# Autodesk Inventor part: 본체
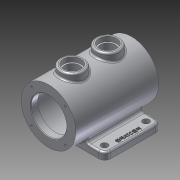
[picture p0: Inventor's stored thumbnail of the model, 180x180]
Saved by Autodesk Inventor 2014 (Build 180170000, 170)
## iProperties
Created: 2014-12
Part Number: 본체
Material: 알루미늄 6061
Document SubType Name: Modeling
Designer: Owner
Density: 2.71 g/cm^3
Appearance: 알루미늄 - 평지
Mass: 1293.91 g
Surface Area: 1040.14 cm^2
Volume: 477.456 cm^3
Author: Owner
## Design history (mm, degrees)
sketch "스케치1"
  geometry: C1 r 46 at (0, 0); 1 further point
  constraints: 1 centre point, 1 coincident
  dimensions: "d0" = 92 diameter of C1
extrude "돌출1" new body sketch "스케치1" stored distance "d1" = 140; taper "d2" = 0 deg
node "작업 평면1"
sketch "스케치2"
  geometry: L1 (-38, 65)-(-50, 65); L2 (-50, 65)-(-50, -65); L3 (-50, -65)-(-38, -65); L4 (-38, 38.884)-(-38, 65); L5 (-38, -38.884)-(-38, -65); A1 r 46 centre (0, 0) between (-38, -25.923) and (-38, 25.923) reference; A2 r 46 centre (0, 0) between (-29.765, -35.072) and (-29.765, 35.072); A3 r 5 centre (-33, 38.884) between (-38, 38.884) and (-29.765, 35.072); A4 r 5 centre (-33, -38.884) between (-29.765, -35.072) and (-38, -38.884); 2 further points
  constraints: 10 end point, 10 point on circle, 4 tangent, 3 centre point, 2 parallel, 2 point on line, 1 coincident, 1 collinear, 1 equal radius, 1 horizontal, 1 horizontal alignment, 1 midpoint, 1 perpendicular
  dimensions: "d4" = 130 distance of L1.end L2.end; "d5" = 50 distance from line of point (0, 0) L2; "d6" = 12 distance of L1.start L1.end; "d7" = 12 distance between parallel lines of L2 L5; "d8" = 5 radius of A3
extrude "돌출2" join sketch "스케치2" distance "d9" = 95; taper "d10" = 0 deg
hole "구멍1" diameter "d13" = 60; stored, may be unused: countersink angle "d17" = 90 deg, drill point angle "d19" = 118 deg; dims "d11" = 10, "d12" = 10, "d14" = 6, "d15" = 4, "d16" = 2, "d18" = 8
node "작업 평면2"
sketch "스케치3"
  geometry: C1 r 37.5 at (0, 0); 1 further point
  constraints: 1 centre point, 1 coincident
  dimensions: "d21" = 75 diameter of C1
extrude "돌출3" cut sketch "스케치3" distance "d22" = 116; taper "d23" = 0 deg
node "작업 평면3"
sketch "스케치4"
  geometry: L1 (-70, 46)-(-70, -46) reference; L2 (70, -46)-(70, 46) reference; C1 r 20 at (-30, 0); C2 r 20 at (30, 0); 1 further point
  constraints: 2 centre point, 2 horizontal alignment
  dimensions: "d25" = 40 diameter of C1; "d27" = 40 distance from line of L1 C1.centre; "d29" = 40 diameter of C2; "d30" = 40 distance from line of L2 C2.centre
extrude "돌출4" join sketch "스케치4" stored distance "d31" = 116; taper "d32" = 0 deg
hole "구멍2" diameter "d35" = 25; stored, may be unused: countersink angle "d39" = 90 deg, drill point angle "d41" = 118 deg; dims "d33" = 10, "d34" = 10, "d36" = 6, "d37" = 30, "d38" = 8, "d40" = 8
hole "구멍3" diameter "d44" = 25; stored, may be unused: countersink angle "d48" = 90 deg, drill point angle "d50" = 118 deg; dims "d42" = 10, "d43" = 10, "d45" = 6, "d46" = 30, "d47" = 8, "d49" = 8
sketch "스케치5"
  geometry: L1 (0, 0)-(26.116, 0) reference; L2 (26.116, -95)-(0, -95) reference; L3 (26.116, 0)-(26.116, -95) reference; 3 further points
  dimensions: "d53" = 13 distance from line of L3 point (13.116, -12.5); "d54" = 12.5 distance from line of L1 point (13.116, -12.5); "d55" = 12.5 distance from line of L2 point (13.116, -82.5); "d56" = 13 distance from line of L3 point (13.116, -82.5)
hole "구멍4" sketch "스케치5" at (13.116, -12.5), (13.116, -82.5) diameter "d57" = 11; stored, may be unused: countersink angle "d61" = 90 deg, drill point angle "d63" = 118 deg; dims "d58" = 6, "d59" = 30, "d60" = 8, "d62" = 8
sketch "스케치6"
  geometry: L1 (26.116, 0)-(26.116, -95) reference; C1 r 5.5 at (13.116, -82.5) reference; 2 further points
  constraints: 1 other
  dimensions: "d64" = 35 vertical distance of C1.centre point (18.116, -47.5); "d65" = 8 distance from line of L1 point (18.116, -47.5)
feature "엠보싱1" sketch "스케치6" dims "d66" = 1, "d67" = 0
fillet "모깎기1" dims "d68" = 10
fillet "모깎기2" dims "d69" = 3
fillet "모깎기3" dims "d70" = 3
fillet "모깎기4" dims "d71" = 3
chamfer "모따기1" distance "d72" = 1; stored, may be unused: second distance "d73" = 2, angle "d74" = 45 deg
chamfer "모따기2" distance "d75" = 1; stored, may be unused: second distance "d76" = 2, angle "d77" = 45 deg
sketch "스케치7"
  geometry: L1 (0, 0)-(28.284, -28.284); L2 (0, 0)-(40, 0); C1 r 31 at (0, 0) reference; 1 further point
  constraints: 4 end point, 1 coincident, 1 equal length, 1 horizontal
  dimensions: "d78" = 40 distance of L1.start L1.end; "d79" = 45 deg angle of L1 L2
hole "구멍5" sketch "스케치7" at (28.284, -28.284) diameter "d80" = 3.242; stored, may be unused: countersink angle "d84" = 90 deg, drill point angle "d86" = 118 deg; dims "d81" = 8, "d82" = 30, "d83" = 8, "d85" = 10
node "솔리드1"
mirror "대칭1"
pattern_circular "원형 패턴1" dims angle "d88" = 360 deg
mirror "대칭2"
other parameters: "d3" = -15, "d20" = -12, "d24" = 56
